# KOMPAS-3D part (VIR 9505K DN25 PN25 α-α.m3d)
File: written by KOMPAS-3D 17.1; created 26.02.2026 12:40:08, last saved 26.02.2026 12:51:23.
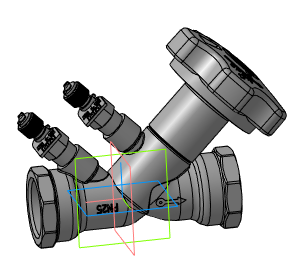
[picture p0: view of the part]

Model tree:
1. Операция без истории:4  (labels: VIR 9505K DN25 PN25 р-р)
